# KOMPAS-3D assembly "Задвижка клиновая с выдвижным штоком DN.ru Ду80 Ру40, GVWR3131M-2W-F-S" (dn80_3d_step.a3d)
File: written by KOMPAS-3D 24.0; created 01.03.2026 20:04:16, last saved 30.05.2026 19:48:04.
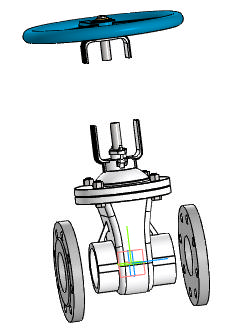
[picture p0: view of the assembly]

Document properties: Автор: R2D2; Полное имя файла: E:\Работа\Зайцев\GVWR3131M-2W-F-S Задвижка клиновая с выдвижным штоком DN.ru Ду50-100 Ру40\исходные материалы\DN80\dn80_3d_step.a3d

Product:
- Component [detail]: Деталь2  | qty 1  | pos. 1  | Масса: 4.922929; Автор: R2D2; additional columns: Типовые; source file: Деталь2 Деталь2.m3d
- Component [detail]: AS 1110 - M12 x 45  | qty 4  | pos. 2  | Масса: 0.056439; Комментарий: Болты и винты   шестигранные точные   метрические ISO; Автор: R2D2; additional columns: Сталь, мягкая; source file: AS 1110 - M12 x 45 AS 1110 - M12 x 45.m3d
- Component [detail]: ANSI B18.2.4.2M - M12x1,75 - 18  | designation ANSI B18.2.4.2M - M12x1,75  | qty 4  | pos. 3  | Масса: 0.018772; Комментарий: Типы метрических   шестигранных гаек   2; Автор: R2D2; additional columns: Сталь, мягкая; source file: ANSI B18.2.4.2M - M12x1,75 ANSI B18.2.4.2M - M12x1,75 - 18.m3d
- Component [detail]: ANSI B18.2.4.2M - M5x0,8 - 8  | designation ANSI B18.2.4.2M - M5x0,8  | qty 2  | pos. 4  | Масса: 0.00167; Комментарий: Типы метрических   шестигранных гаек   2; Автор: R2D2; additional columns: Сталь, мягкая; source file: ANSI B18.2.4.2M - M5x0,8 ANSI B18.2.4.2M - M5x0,8 - 8.m3d
- Component [detail]: Деталь1  | qty 1  | pos. 5  | Масса: 23.507576; additional columns: Типовые; source file: 2.m3d
- Component [detail]: Деталь1  | qty 1  | pos. 5  | Масса: 0.546953; Автор: R2D2; additional columns: Типовые; source file: 3.m3d
- Component [detail]: Деталь1  | qty 2  | pos. 5  | Масса: 4.236703; Автор: R2D2; additional columns: Типовые; source file: 1.m3d
- Part/product: Задвижка клиновая с выдвижным штоком DN.ru Ду80 Ру40  | designation GVWR3131M-2W-F-S
    Масса: 31
    Раздел спецификации: Прочие изделия
    Примечание: D040-07874

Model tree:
1. Массив по концентрической сетке:1  (labels: Грань.Твердое тело1)  (4 pattern instances)
     Шаг 2 = 360
2. Массив по концентрической сетке:2  (with: Грань.Элемент вращения:1)  (labels: Грань.Твердое тело1; Грань.Solid1)  (2 pattern instances)
     Шаг 2 = 360; Расстояние = -495; Расстояние = -140; Ориентация = 2

Referenced files in E:\Работа\Зайцев\GVWR3131M-2W-F-S Задвижка клиновая с выдвижным штоком DN.ru Ду50-100 Ру40\исходные материалы\DN80\: Деталь2 Деталь2.m3d, AS 1110 - M12 x 45 AS 1110 - M12 x 45.m3d, ANSI B18.2.4.2M - M12x1,75 ANSI B18.2.4.2M - M12x1,75 - 18.m3d, ANSI B18.2.4.2M - M5x0,8 ANSI B18.2.4.2M - M5x0,8 - 8.m3d, 2.m3d, 1.m3d, 3.m3d
Referenced files in E:\Работа\Зайцев\GVWR3131M-2W-F-S Задвижка клиновая с выдвижным штоком DN.ru Ду50-200 Ру63\DN80\исходные материалы\: 1.m3d, ANSI B18.2.4.2M - M12x1,75 ANSI B18.2.4.2M - M12x1,75 - 18.m3d, AS 1110 - M12 x 45 AS 1110 - M12 x 45.m3d, ANSI B18.2.4.2M - M5x0,8 ANSI B18.2.4.2M - M5x0,8 - 8.m3d
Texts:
  Программные изделия  и базы данных
  ANSI B18.2.4.2M - M12x1,75
  ANSI B18.2.4.2M - M5x0,8
  GVWR3131M-2W-F-S
  Деталь2 Деталь2
  AS 1110 - M12 x 45 AS 1110 - M12 x 45 (1)
  ANSI B18.2.4.2M - M12x1,75 ANSI B18.2.4.2M - M12x1,75 - 18 (1)
  ANSI B18.2.4.2M - M5x0,8 ANSI B18.2.4.2M - M5x0,8 - 8 (1)
  Деталь1 Деталь1
  Деталь1 Деталь1 (1)
  Деталь1 Деталь1 (2)
  ANSI B18.2.4.2M - M12x1,75 ANSI B18.2.4.2M - M12x1,75 - 18 (2)
  AS 1110 - M12 x 45 AS 1110 - M12 x 45 (2)
  ANSI B18.2.4.2M - M12x1,75 ANSI B18.2.4.2M - M12x1,75 - 18 (3)
  AS 1110 - M12 x 45 AS 1110 - M12 x 45 (3)
  ANSI B18.2.4.2M - M12x1,75 ANSI B18.2.4.2M - M12x1,75 - 18 (4)
  AS 1110 - M12 x 45 AS 1110 - M12 x 45 (4)
  ANSI B18.2.4.2M - M5x0,8 ANSI B18.2.4.2M - M5x0,8 - 8 (2)
  Ось Y.Начало координат
  Ось Z.Начало координат
  Плоскость ZX.Начало координат
  Плоскость XY.Начало координат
